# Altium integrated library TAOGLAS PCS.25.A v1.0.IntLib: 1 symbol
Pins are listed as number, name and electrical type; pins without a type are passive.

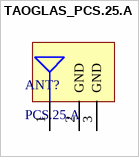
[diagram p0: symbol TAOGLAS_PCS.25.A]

## TAOGLAS_PCS.25.A
designator ANT?, comment PCS.25.A
Wi-Fi / Bluetooth 2.4GHz FR4 Chip Antenna; ComponentLibStatus: Created; MFG: Taoglas; Temp_High: +85C; Temp_Low: -40C
footprint TAOGLAS_PCS.25.A (Wi-Fi / Bluetooth 2.4GHz FR4 Chip Antenna)
footprint TAOGLAS_PCS.25.A_NoClearance (Wi-Fi / Bluetooth 2.4GHz FR4 Chip Antenna)
pins: 1 RF FEED, 2 GND, 3 GND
